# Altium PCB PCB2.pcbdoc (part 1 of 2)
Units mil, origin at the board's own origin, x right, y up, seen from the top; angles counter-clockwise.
Board outline 3540 x 3355 mil, 4 copper layers (Top Layer, GND, PWR, Bottom Layer), stack 62.5 mil thick; 130 components, 101 nets, 421 pads, 287 vias.
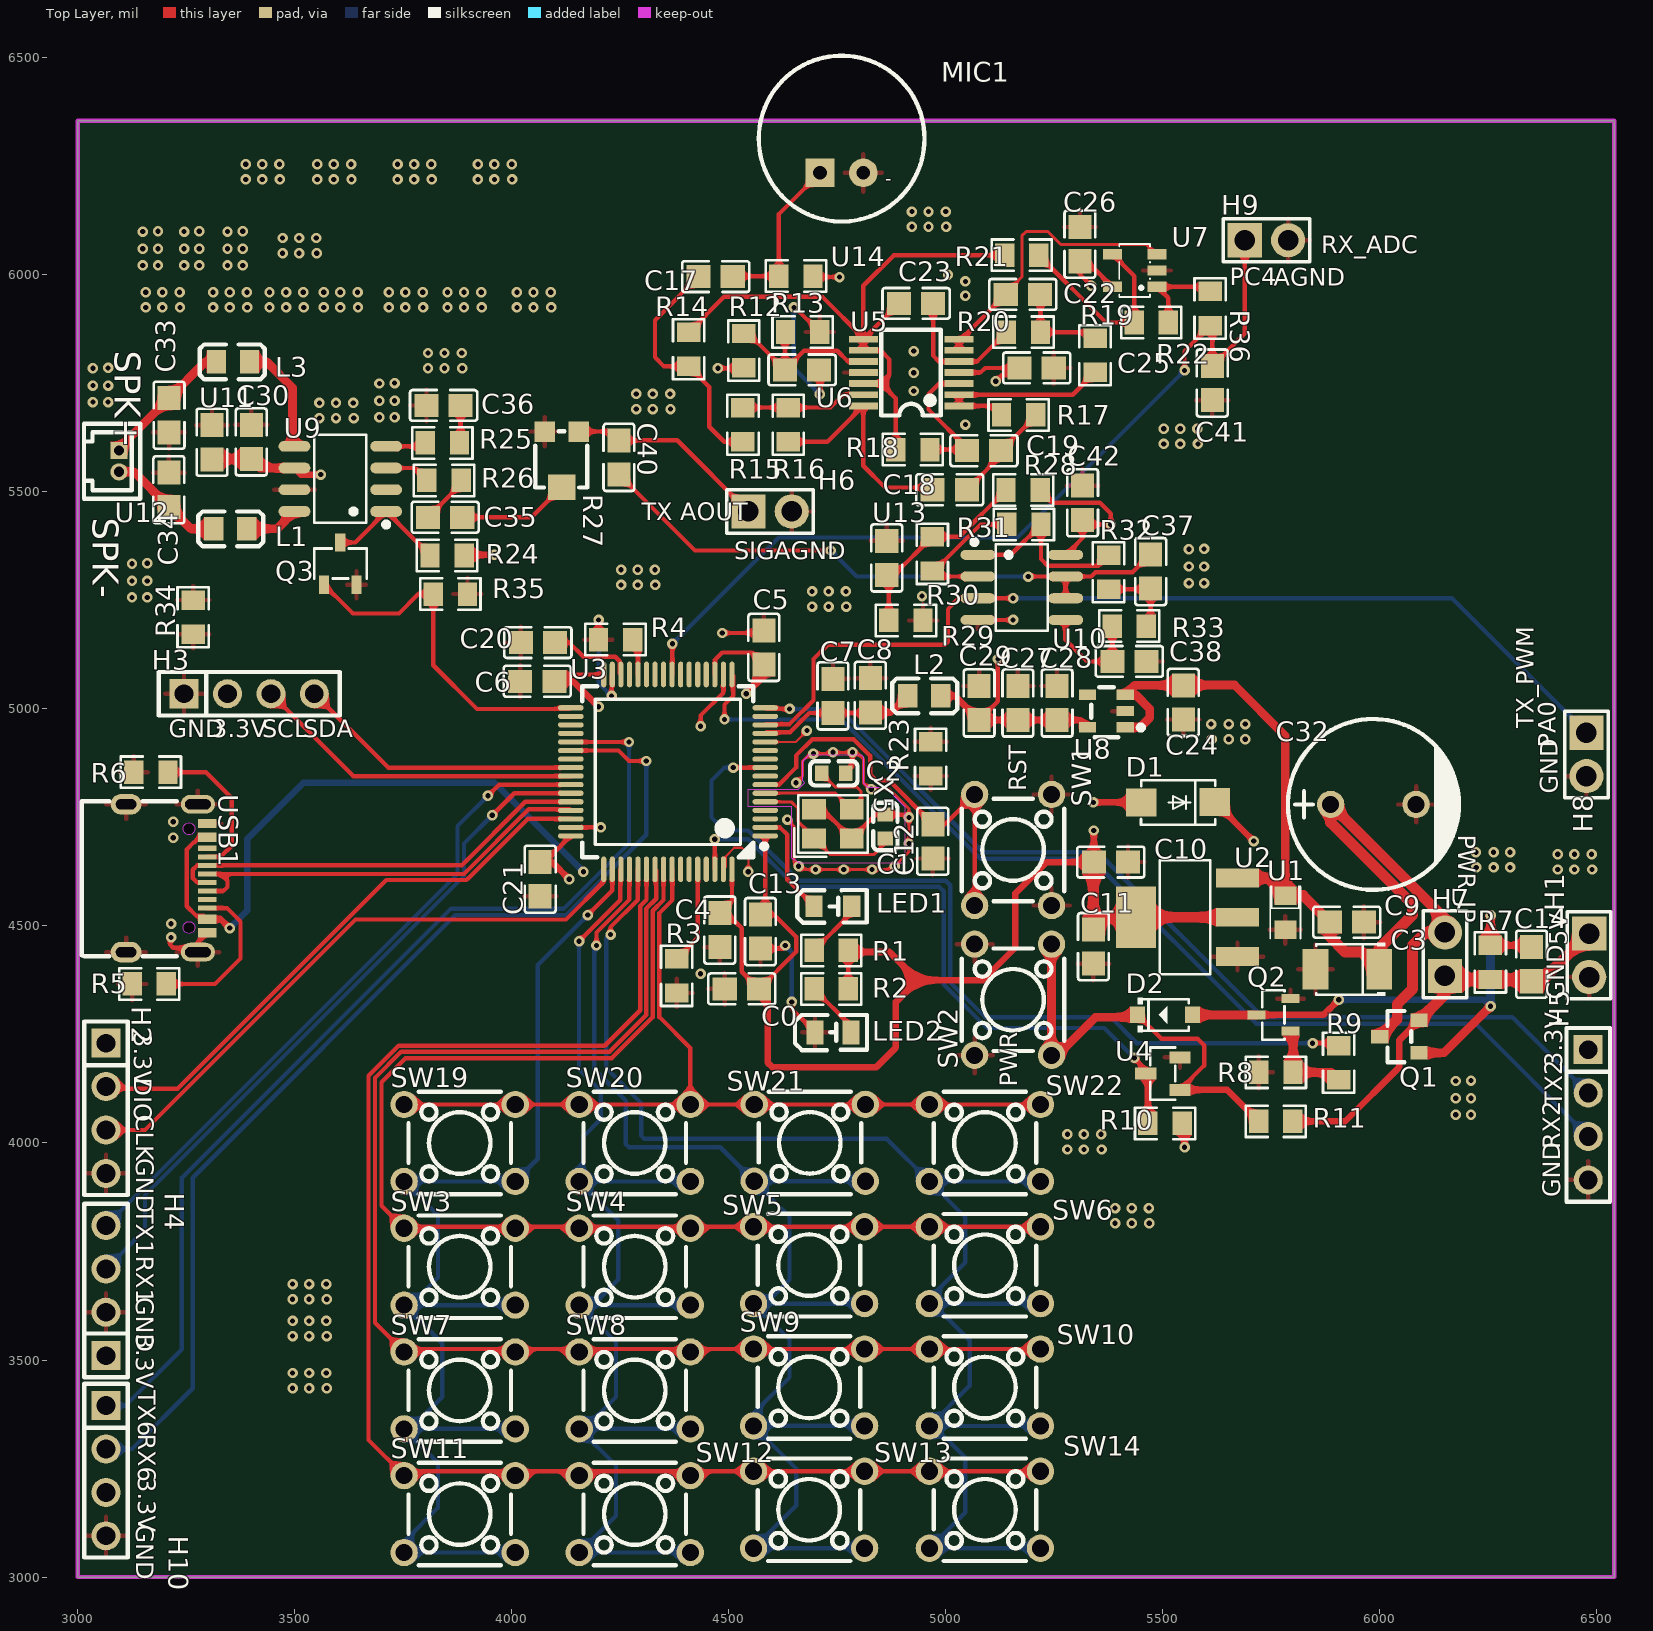
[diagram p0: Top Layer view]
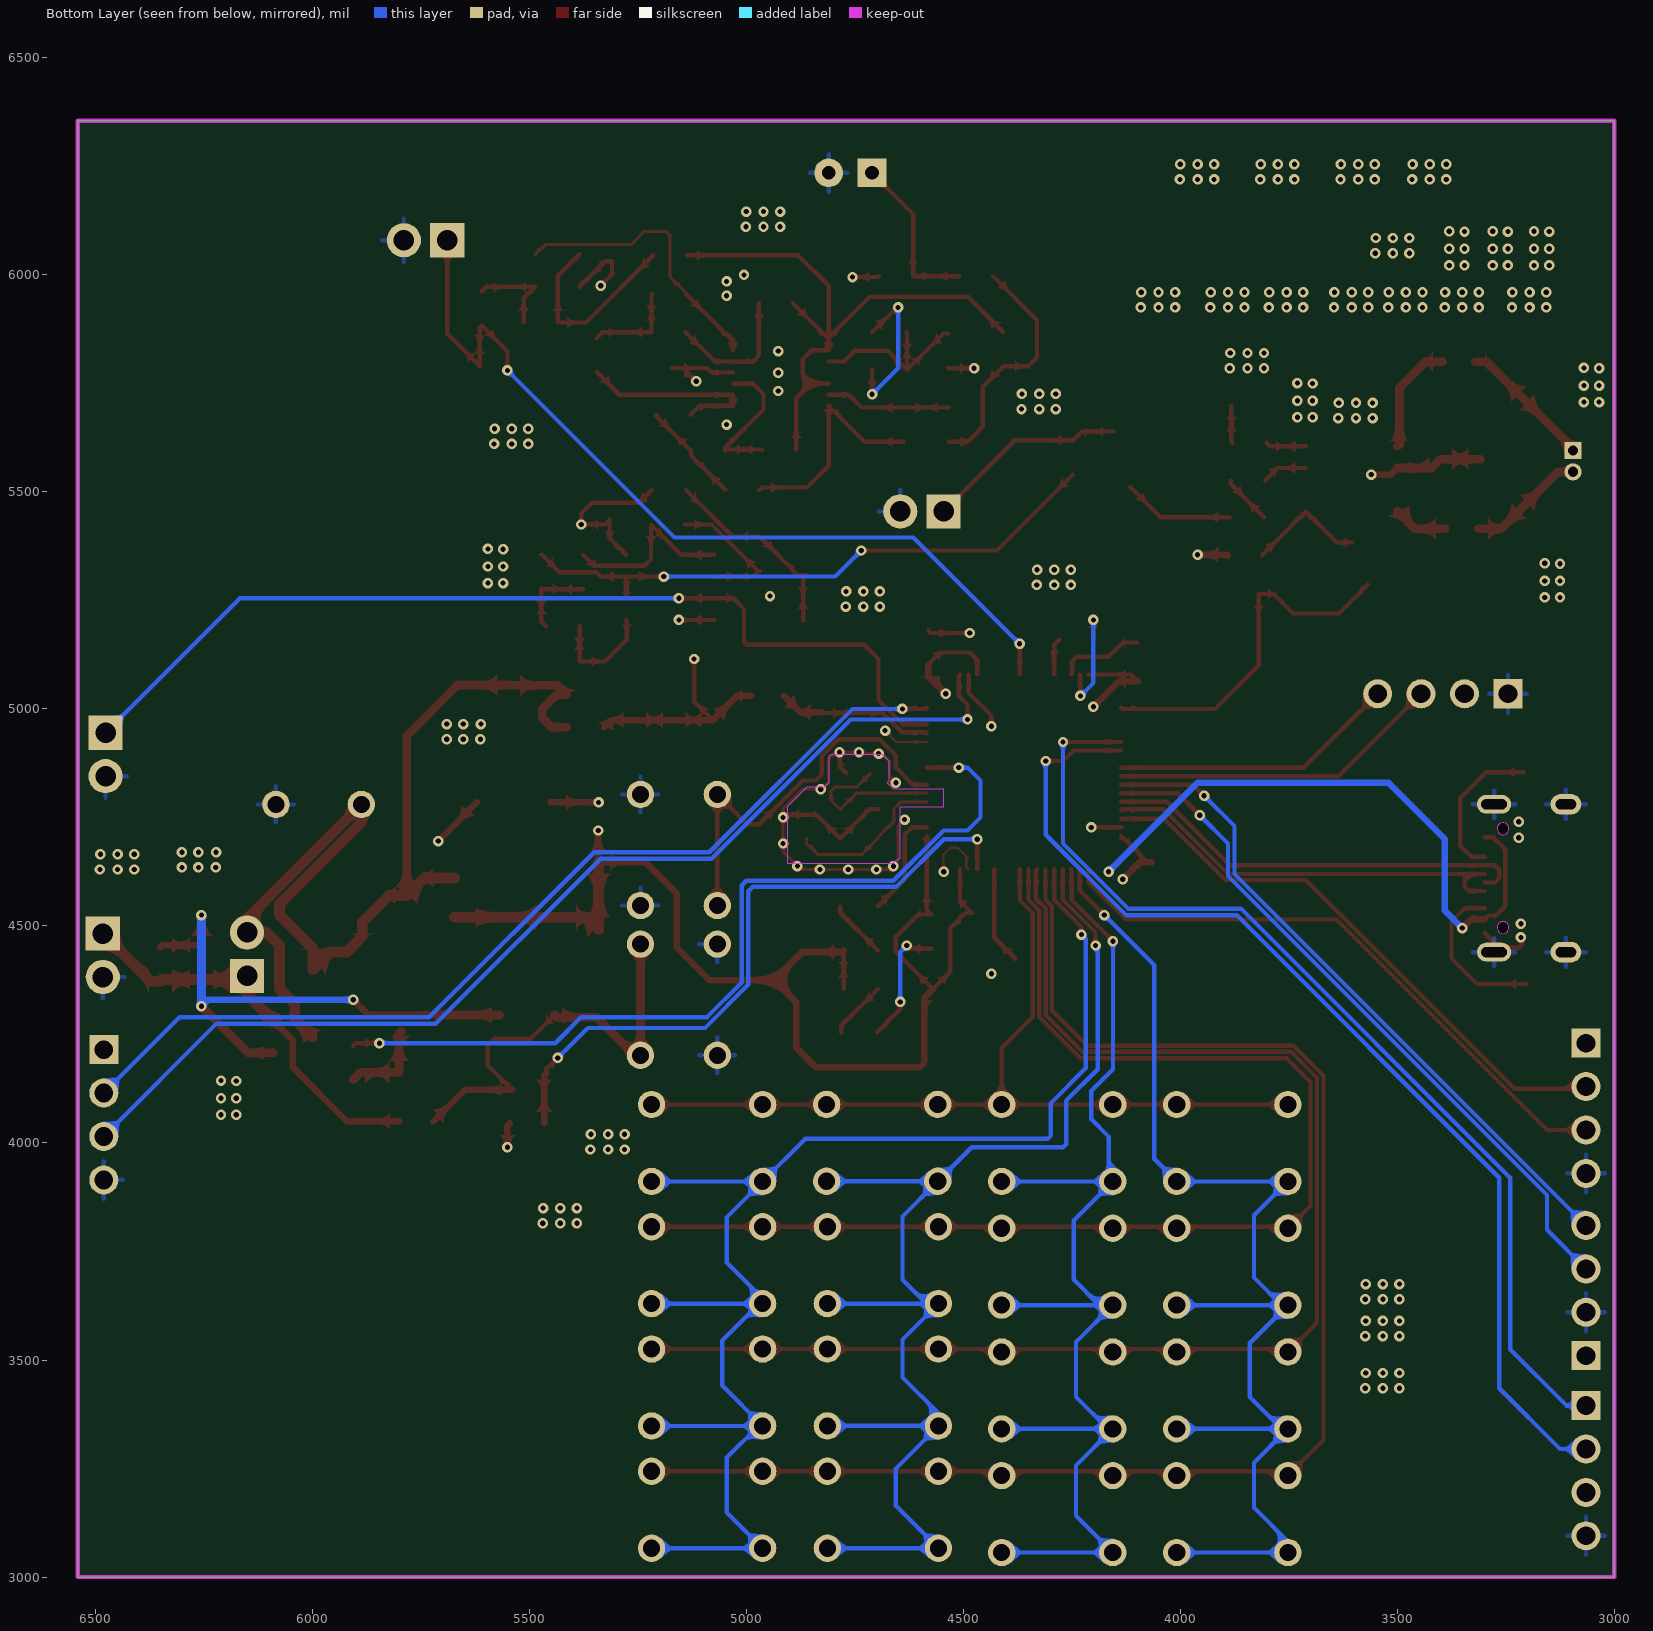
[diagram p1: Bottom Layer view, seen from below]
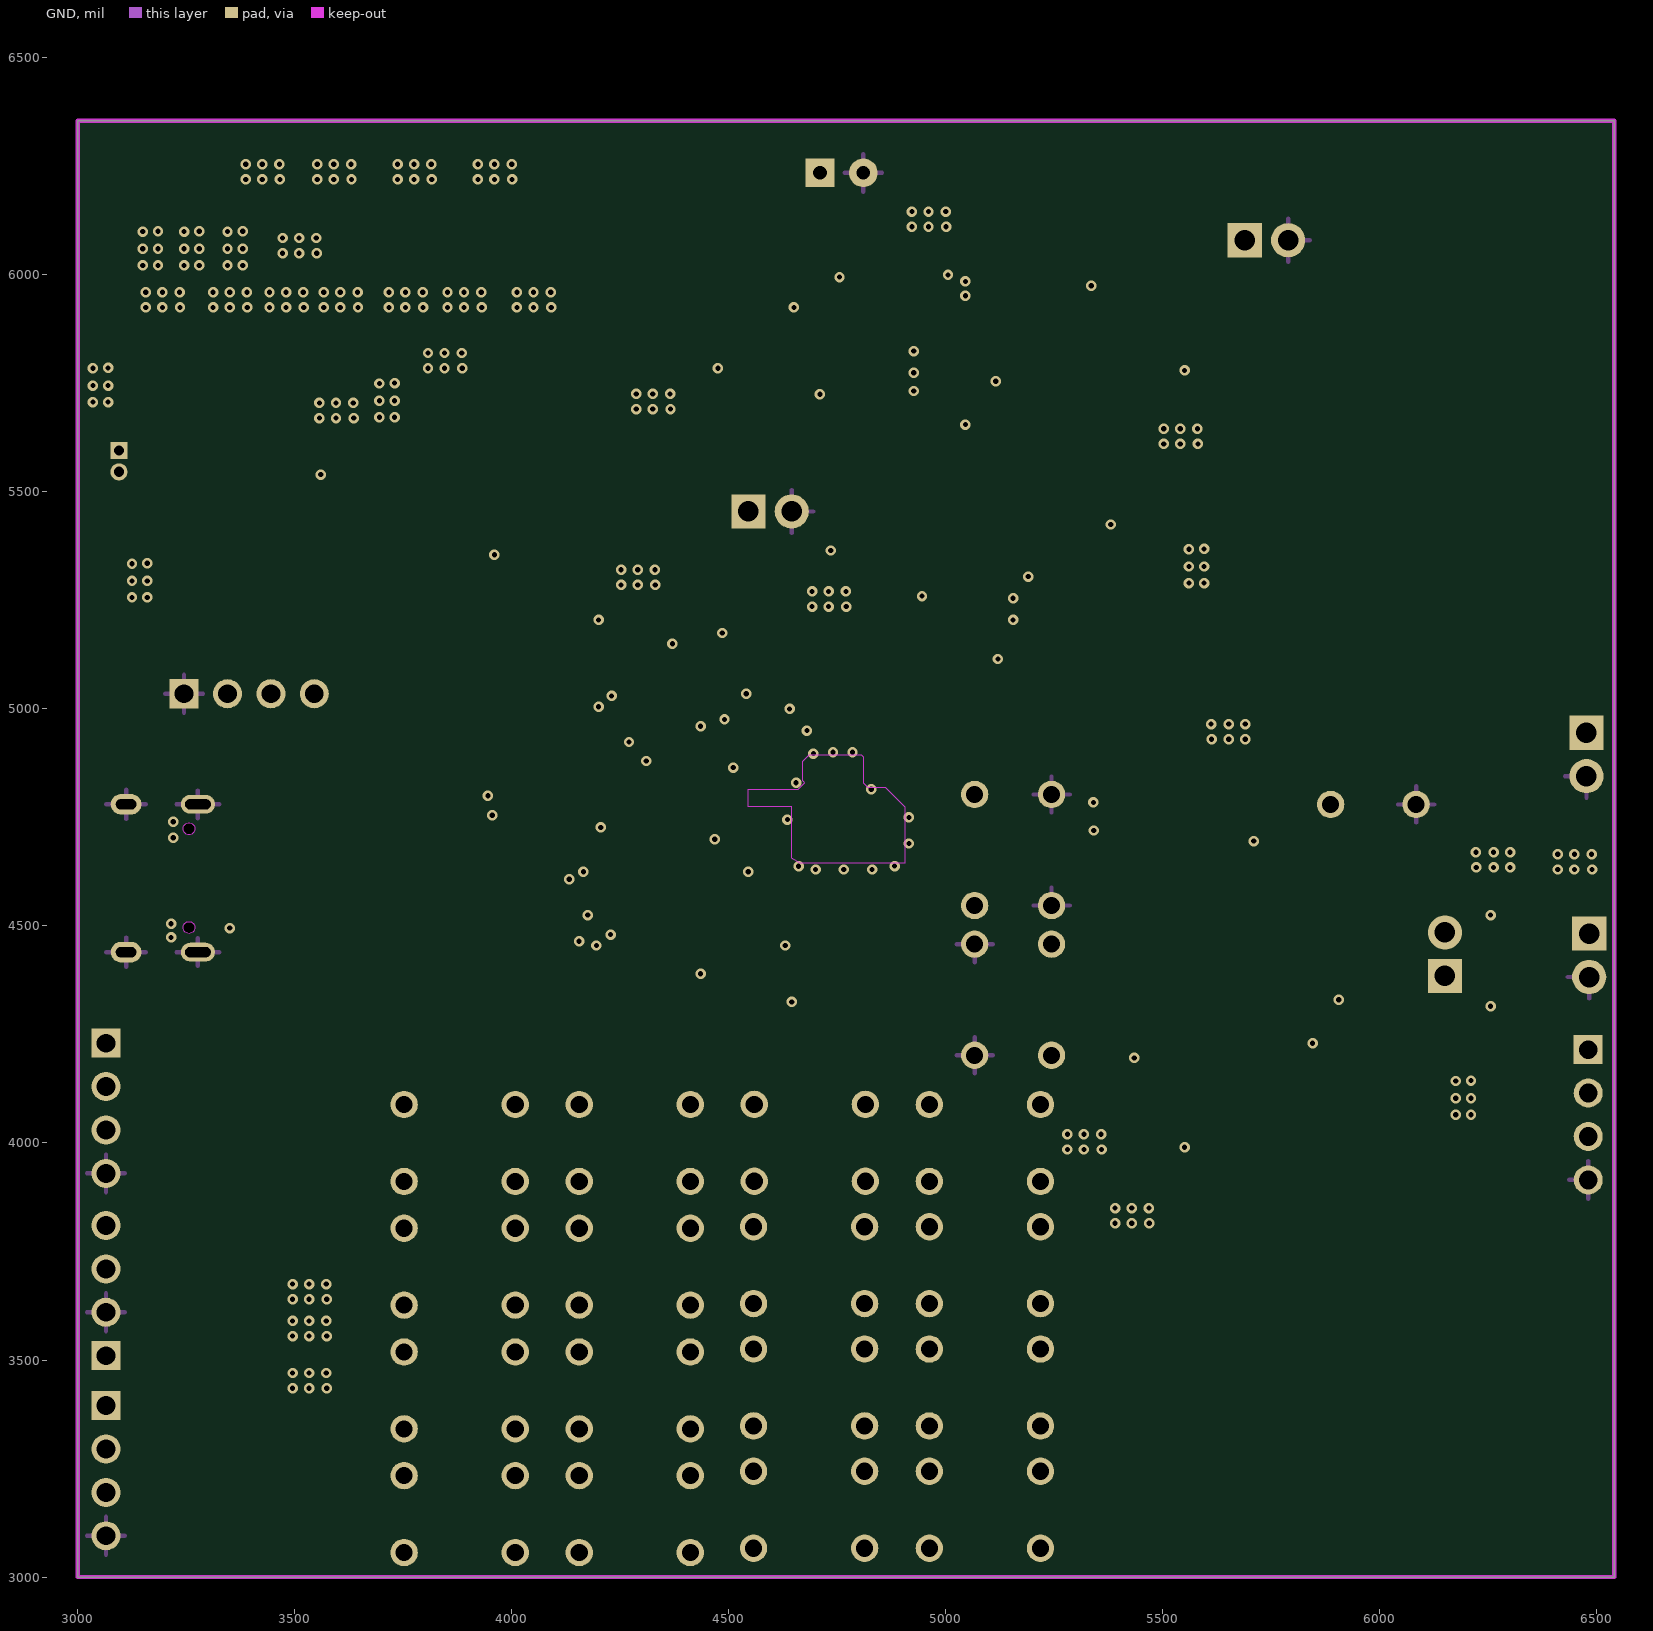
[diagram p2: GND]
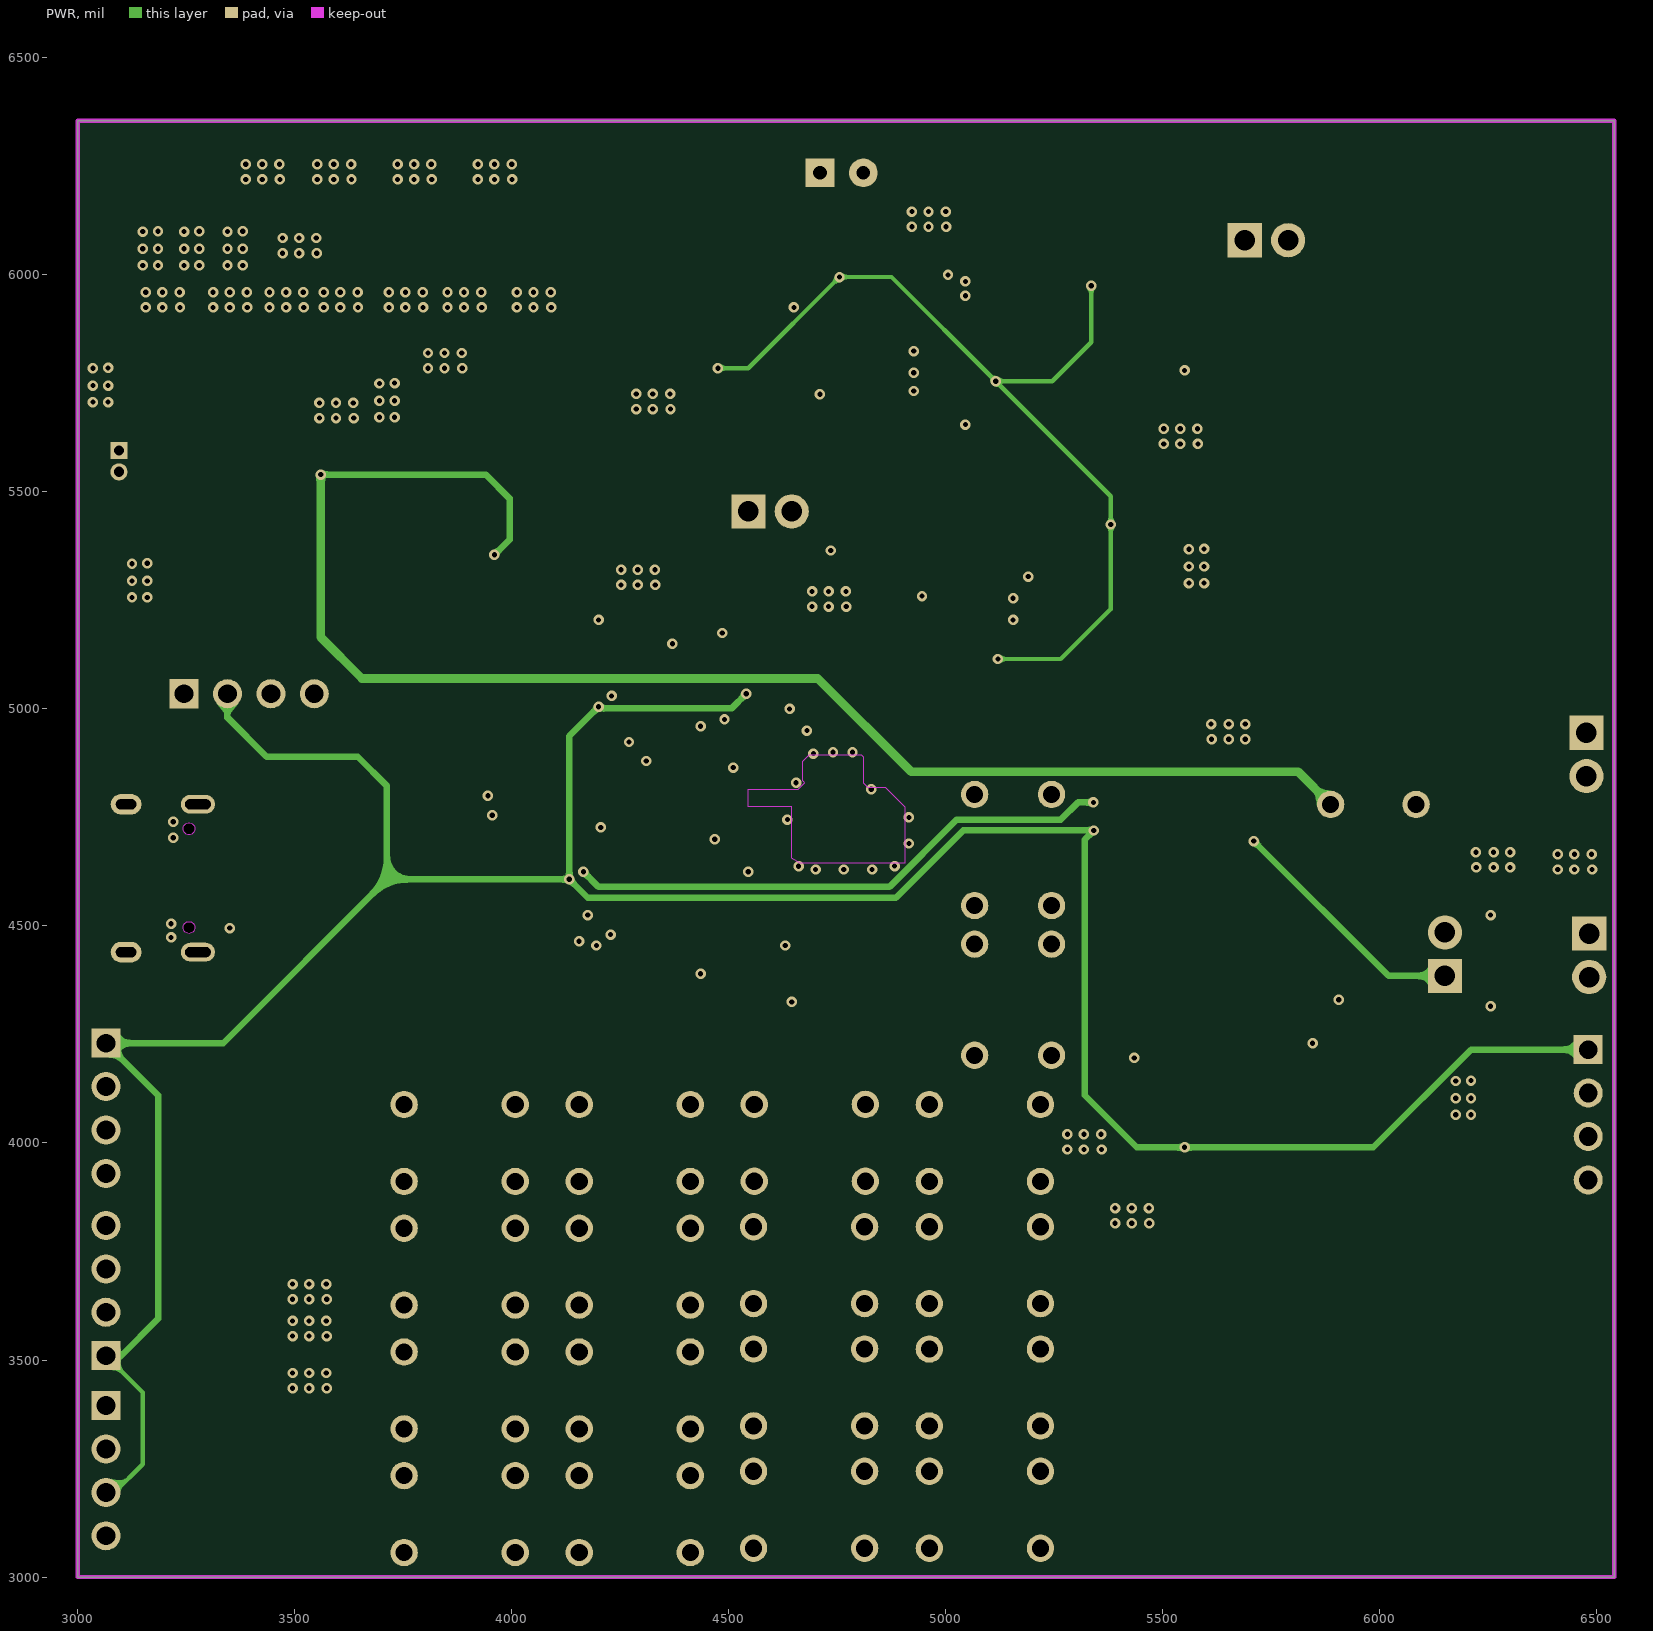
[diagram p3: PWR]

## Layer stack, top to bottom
Top Layer: signal copper 1.4
Dielectric1: surface 8.3, 7628 RC49% 8.6mil, Dk 0
GND: signal copper 0.6
Dielectric2: surface 41.9, 1.1mm H/HOZ Copper, Dk 0
PWR: signal copper 0.6
Dielectric3: surface 8.3, 7628 RC49% 8.6mil, Dk 0
Bottom Layer: signal copper 1.4

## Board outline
3000,6355 3000,3000 6540,3000 6540,6355

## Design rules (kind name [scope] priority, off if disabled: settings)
BoardOutlineClearance copperThickness1oz [All] p0: genericclearance=10 ignorepadtopadclearanceinfootprint=FALSE except(0: Arc-SplitContinuation Track-SplitContinuation SMDPad-SplitContinuation THPad-SplitContinuation Via-SplitContinuation Fill-SplitContinuation Poly-SplitContinuation Region-SplitContinuation Text-SplitContinuation)
BoardOutlineClearance copperThickness2oz [All] p0: genericclearance=10 ignorepadtopadclearanceinfootprint=FALSE except(0: Arc-SplitContinuation Track-SplitContinuation SMDPad-SplitContinuation THPad-SplitContinuation Via-SplitContinuation Fill-SplitContinuation Poly-SplitContinuation Region-SplitContinuation Text-SplitContinuation)
BoardOutlineClearance otherClearance [All] p0: genericclearance=10 ignorepadtopadclearanceinfootprint=FALSE except(0: Arc-SplitContinuation Track-SplitContinuation SMDPad-SplitContinuation THPad-SplitContinuation Via-SplitContinuation Fill-SplitContinuation Poly-SplitContinuation Region-SplitContinuation Text-SplitContinuation)
Clearance copperThickness1oz [All] p1: gap=7 ignorepadtopadclearanceinfootprint=FALSE
Clearance copperThickness2oz [All] p1: gap=7 ignorepadtopadclearanceinfootprint=FALSE
Clearance otherClearance [All] p1: gap=7 ignorepadtopadclearanceinfootprint=FALSE
DiffPairsRouting differentialPair [All] p1: maxuncoupledlength=10 minlimit=6 maxlimit=Infinity mostfreqgap=6 toplayer_minwidth=5 toplayer_prefwidth=10 toplayer_maxwidth=100 bottomlayer_minwidth=5 bottomlayer_prefwidth=10 bottomlayer_maxwidth=100 midlayer1_minwidth=5 midlayer1_prefwidth=10 midlayer1_maxwidth=100 midlayer2_minwidth=5 midlayer2_prefwidth=10 midlayer2_maxwidth=100
PasteMaskExpansion pasteMaskExpansion [All] p1: expansion=0
PlaneConnect innerPlane [All] p1: planeconnectstyle=Relief reliefexpansion=20 reliefentries=4 reliefconductorwidth=10 reliefairgap=10
PolygonConnect copperRegion [All] p1: connectstyle=Relief reliefentries=4 reliefconductorwidth=10 polygonreliefangle="90 Angle" airgapwidth=10
RoutingVias viaSize [All] p1: viastyle="Through Hole" holewidth=12.0078 minholewidth=11.811 maxholewidth=248.0314 width=12.0078 minwidth=11.811 maxwidth=248.0314
SolderMaskExpansion solderMaskExpansion [IsVia] p1: useseparateexpansions=TRUE expansion=-1000 expansionbottom=-1000
SolderMaskExpansion solderMaskExpansion [All] p2: useseparateexpansions=TRUE expansion=2 expansionbottom=2
Width copperThickness1oz [All] p1: maxlimit=100 minlimit=5 preferedwidth=10
Width copperThickness2oz [All] p1: maxlimit=100 minlimit=8 preferedwidth=10

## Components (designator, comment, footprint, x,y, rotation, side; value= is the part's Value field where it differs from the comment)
C0 "4.7uF" C0805#1 4530,4355 r0 top
C1 "8pF" C0603 4860.8,4729 r270 top
C2 "8pF" C0603 4741.9,4851.6 r180 top
C3 "100uF" CASE-B_3528 5925,4400 r180 top
C4 "100nF" C0805#2 4479.4,4490.6 r90 top
C5 "100nF" C0805#2 4580.8,5141.6 r270 top
C6 "100nF" C0805#2 4058.7,5063.7 r0 top
C7 "100nF" C0805#1 4740,5030 r270 top
C8 "1uF" C0805#2 4826.1,5031.6 r270 top
C9 "100nF" C0805#3 5923.7,4508.7 r180 top
C10 "100nF" C0805#3 5380.2,4647.3 r180 top
C11 "10uF" C0805#3 5340,4452.5 r90 top
C12 "100nF" C0805#1 4970,4695 r90 top
C13 "100nF" C0805#3 4572.9,4487.1 r90 top
C14 "1uF" C0805#3 6349.4,4412.1 r90 top
C17 "1uF" C0805#2 4469.8,5996.1 r180 top
C18 "100nF" C0805#1 5009,5505 r0 top
C19 "100nF" C0805#3 5087.7,5595 r180 top
C20 "4.7uF" C0805#2 4060.3,5152.9 r0 top
C21 "100nF" C0805#2 4065.5,4607.8 r90 top
C22 "2.2nF" C0805#2 5177.5,5955 r180 top
C23 "1nF" C0805#3 4931.4,5934.3 r0 top
C24 "1uF" C0805#1 5547.1,5014.9 r90 top
C25 "100nF" C0805#3 5209.4,5785.6 r0 top
C26 "100nF" C0805#1 5309,6070.9 r90 top
C27 "2.2uF" C0805#2 5166,5013.7 r270 top
C28 "10uF" C0805#2 5256.3,5013.7 r270 top
C29 "100nF" C0805#2 5076.6,5013.7 r270 top
C30 "1uF" C0805#1 3400,5615 r270 top
C32 "470uF" CAP-TH_BD10.0-P5.00-D0.6-FD 5985,4780 r0 top
C33 "220pF" C0805#3 3210.5,5676.7 r90 top
C34 "220pF" C0805#1 3210,5505 r90 top
C35 "1uF" C0805#3 3846.5,5441.5 r180 top
C36 "1uF" C0805#1 3842.8,5699.1 r0 top
C37 "1.8nF" C0805#2 5472,5316.5 r270 top
C38 "1.8nF" C0805#2 5422.9,5109.3 r0 top
C40 "1uF" C0805#2 4247,5579.5 r270 top
C41 "2.2nF" C0805#1 5614,5750.9 r90 top
C42 "100nF" C0805#1 5315,5475 r90 top
D1 "SS14" SMA_L4.3-W2.6-LS5.0-FD 5535,4785 r0 top
D2 "B5817W" SOD-123_L2.7-W1.6-LS3.7-FD 5505,4295 r180 top
H1 "PZ254V-11-02P" HDR-TH_2P-P2.54-V-M 6482.2,4432.3 r270 top
H2 "PZ254V-11-04P" HDR-TH_4P-P2.54-V-M 3065,4080 r270 top
H3 "PM254V-11-04-H85" HDR-TH_4P-P2.54-V-F 3395,5035 r0 top
H4 "PZ254V-11-04P" HDR-TH_4P-P2.54-V-M 3065,3660 r90 top
H5 "PZ254V-11-04P" HDR-TH_4P-P2.54-V-M 6480,4065 r270 top
H6 "PZ254V-11-02P" HDR-TH_2P-P2.54-V-M 4595,5455 r0 top
H7 "PZ254V-11-02P" HDR-TH_2P-P2.54-V-M 6150,4435 r90 top
H8 "PZ254V-11-02P" HDR-TH_2P-P2.54-V-M 6475.9,4895.1 r270 top
H9 "PZ254V-11-02P" HDR-TH_2P-P2.54-V-M 5738.6,6079.8 r0 top
H10 "PZ254V-11-04P" HDR-TH_4P-P2.54-V-M 3065,3245 r270 top
L1 "BLM21PG221SN1D" L0805#1 3351.1,5415 r180 top
L2 "CBW201209U102T" L0805#2 4950,5030 r180 top
L3 "BLM21PG221SN1D" L0805#3 3357.7,5799.7 r0 top
LED1 "GL0805UB01" LED0805-RD_BLUE 4740,4545 r0 top
LED2 "GL0805UR01" LED0805-R-RD_RED 4740,4255 r0 top
MIC1 "GMI9745P-56DB" MIC-TH_BD9.7-P2.54-D0.8-L-FD 4760,6235 r0 top
Q1 "AO3401A" SOT-23_L2.9-W1.3-P1.90-LS2.4-BR 6045,4245 r0 top
Q2 "S8050" SOT-23-3_L2.9-W1.3-P1.90-LS2.3-BR 5755,4295 r0 top
Q3 "2N7002K-T1-GE3" SOT-23-3_L2.9-W1.6-P1.90-LS2.8-BR 3605,5335 r270 top
R1 "1.5kΩ" R0805#1 4735.9,4443.5 r180 top
R2 "5.1kΩ" R0805#1 4735.9,4354.8 r180 top
R3 "10kΩ" R0805#1 4380,4385 r270 top
R4 "10kΩ" R0805#2 4239.1,5159.7 r180 top
R5 "5.1kΩ" R0805#3 3164.9,4366.4 r0 top
R6 "5.1kΩ" R0805#1 3168.6,4854.3 r180 top
R7 "100kΩ" R0805#2 6254.4,4416 r270 top
R8 "100kΩ" R0805#3 5760.6,4162.8 r0 top
R9 "10kΩ" R0805#1 5905,4185 r270 top
R10 "10kΩ" R0805#1 5505,4045 r0 top
R11 "100kΩ" R0805#1 5760,4050 r0 top
R12 "10kΩ" R0805#2 4534.4,5825.6 r90 top
R13 "10kΩ" R0805#1 4670,5868.4 r0 top
R14 "100kΩ" R0805#1 4407.6,5828.6 r270 top
R15 "4.7kΩ" R0805#1 4532.6,5654.9 r90 top
R16 "100kΩ" R0805#1 4636.9,5654.9 r90 top
R17 "1.5kΩ" R0805#3 5167.7,5677.4 r180 top
R18 "3.3kΩ" R0805#1 4924,5597.6 r0 top
R19 "15kΩ" R0805#1 5343.9,5814.9 r90 top
R20 "15kΩ" R0805#2 5178.9,5868 r180 top
R21 "47kΩ" R0805#2 5174.7,6045.3 r0 top
R22 "47kΩ" R0805#3 5473.3,5890.3 r180 top
R23 "0Ω" R0805#1 4965,4885 r270 top locked
R24 "10kΩ" R0805#2 3850.9,5353.5 r180 top
R25 "100Ω" R0805#3 3840.1,5612.9 r180 top
R26 "100Ω" R0805#2 3843.9,5526.5 r180 top
R27 "10kΩ" RES-ADJ-SMD_JER33X-1-14 4115,5575 r180 top
R28 "10kΩ" R0805#1 5178.1,5504.4 r180 top
R29 "10kΩ" R0805#3 4908.2,5203.8 r0 top
R30 "47kΩ" R0805#3 4968.9,5357.2 r270 top
R31 "47kΩ" R0805#1 5180,5425 r180 top
R32 "10kΩ" R0805#1 5375,5315 r270 top
R33 "10kΩ" R0805#3 5422.6,5190.9 r180 top
R34 "0Ω" R0805#1 3266.1,5211.4 r90 top
R35 "100kΩ" R0805#2 3858.6,5264.7 r180 top
R36 "1kΩ" R0805#3 5609,5922.5 r270 top
SW1 "SH-6X6X4.3H-CJ" SW-TH_SH-6X6X4.3H-CJ#1 5155,4675 r90 top
SW2 "SH-6X6X4.3H-CJ" SW-TH_SH-6X6X4.3H-CJ#1 5155,4330 r90 top
SW3 "SH-6X6X4.3H-CJ" SW-TH_SH-6X6X4.3H-CJ#1 3880,3715 r0 top
SW4 "SH-6X6X4.3H-CJ" SW-TH_SH-6X6X4.3H-CJ#2 4283.3,3715 r0 top
SW5 "SH-6X6X4.3H-CJ" SW-TH_SH-6X6X4.3H-CJ#3 4685,3718.6 r0 top
SW6 "SH-6X6X4.3H-CJ" SW-TH_SH-6X6X4.3H-CJ#4 5090,3718.3 r0 top
SW7 "SH-6X6X4.3H-CJ" SW-TH_SH-6X6X4.3H-CJ#1 3880,3430 r0 top
SW8 "SH-6X6X4.3H-CJ" SW-TH_SH-6X6X4.3H-CJ#2 4283.3,3430 r0 top
SW9 "SH-6X6X4.3H-CJ" SW-TH_SH-6X6X4.3H-CJ#1 4685,3436.8 r0 top
SW10 "SH-6X6X4.3H-CJ" SW-TH_SH-6X6X4.3H-CJ#3 5090,3436.7 r0 top
SW11 "SH-6X6X4.3H-CJ" SW-TH_SH-6X6X4.3H-CJ#1 3880,3145 r0 top
SW12 "SH-6X6X4.3H-CJ" SW-TH_SH-6X6X4.3H-CJ#2 4283.3,3145 r0 top
SW13 "SH-6X6X4.3H-CJ" SW-TH_SH-6X6X4.3H-CJ#1 4685,3155 r0 top
SW14 "SH-6X6X4.3H-CJ" SW-TH_SH-6X6X4.3H-CJ#1 5090,3155 r0 top
SW19 "SH-6X6X4.3H-CJ" SW-TH_SH-6X6X4.3H-CJ#1 3880,4000 r0 top
SW20 "SH-6X6X4.3H-CJ" SW-TH_SH-6X6X4.3H-CJ#2 4283.3,4000 r0 top
SW21 "SH-6X6X4.3H-CJ" SW-TH_SH-6X6X4.3H-CJ#5 4686.7,4000.3 r0 top
SW22 "SH-6X6X4.3H-CJ" SW-TH_SH-6X6X4.3H-CJ#1 5090,4000 r0 top
U1 "10uF" CAP-SMD_L2.0-W1.3-FD 5782.3,4530.4 r270 top
U2 "AMS1117-3.3" SOT-223-3_L6.5-W3.4-P2.30-LS7.0-BR 5555,4520 r0 top
U3 "STM32F411RET6" LQFP-64_L10.0-W10.0-P0.50-LS12.0-BL 4360,4855 r90 top locked
U4 "2N7002K" SOT-23-3_L2.9-W1.3-P0.95-LS2.4-BR 5500,4160 r0 top
U5 "MCP6004T-I/ST" TSSOP-14_L5.0-W4.4-P0.65-LS6.4-BL 4920,5775 r90 top
U6 "10uF" C0805#3 4668.7,5781.1 r180 top
U7 "MCP6001T-I/OT" SOT-23-5_L3.0-W1.7-P0.95-LS2.8-BR 5435,6010 r0 top
U8 "TPS7A2033PDBVR" SOT-23-5_L2.9-W1.6-P0.95-LS2.8-BR 5370,4995 r0 top
U9 "PAM8302AADCR" SOP-8_L4.9-W3.9-P1.27-LS6.0-BL 3605,5530 r90 top
U10 "MCP6002T-I/SN" SOIC-8_L4.9-W3.9-P1.27-LS6.0-BL 5175,5280 r270 top
U11 "10uF" C0805#2 3309.4,5614.4 r270 top
U12 "ZX-MX1.25-2PZZ" CONN-TH_2P-P1.25_MEGASTAR_ZX-MX1.25-2PZZ 3095,5570.8 r270 top
U13 "10uF" C0805#2 4863.9,5347.9 r270 top
U14 "2.2kΩ" R0805#3 4654.8,5997.2 r0 top
USB1 "TYPE-C 16PIN 2MD(073)" USB-C-SMD_TYPE-C-16PIN-2MD-073 3205,4610 r270 top
X5 "25MHz" CRYSTAL-SMD_4P-L3.2-W2.5-BL 4740,4735 r0 top

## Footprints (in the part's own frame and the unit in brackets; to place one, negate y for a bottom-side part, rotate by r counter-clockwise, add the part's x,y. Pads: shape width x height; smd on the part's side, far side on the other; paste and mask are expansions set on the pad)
C0603 [mil]
  rect 31.5x35.4 smd: 1(-27.6,0) 2(27.6,0)
  silkscreen extent -55,-28 55,28
C0805#1 [mil]
  rect 55.5x53.1 smd paste-3937 mask+2: 1(-39.4,0) 2(39.4,0)
  silkscreen extent -77,-36 77,36
C0805#2 [mil]
  rect 55.5x53.1 smd paste-3937 mask+2: 1(-39.3,0) 2(39.4,0)
  silkscreen extent -77,-36 77,36
C0805#3 [mil]
  rect 55.5x53.1 smd paste-3937 mask+2: 1(-39.4,0) 2(39.3,0)
  silkscreen extent -77,-36 77,36
CAP-SMD_L2.0-W1.3-FD [mil]
  rect 43.3x51.2 smd paste+0 mask+2: 1(-39.4,0) 2(39.3,0)
  silkscreen extent -62,-35 60,35
CAP-TH_BD10.0-P5.00-D0.6-FD [mil]
  round 63 hole 39.4 paste+0 mask+2: 1(-98.4,0) 2(98.4,0)
  silkscreen extent -197,-197 200,197
CASE-B_3528 [mil]
  rect 59.3x93.5 smd: 1(-73.3,0) 2(73.2,0)
  silkscreen extent -87,-61 72,61
CONN-TH_2P-P1.25_MEGASTAR_ZX-MX1.25-2PZZ [mil]
  rect 39.4x39.4 hole 23.6: 1(-24.6,0)
  round 39.4 hole 23.6: 2(24.6,0)
  silkscreen extent -87,-81 87,49
CRYSTAL-SMD_4P-L3.2-W2.5-BL [mil]
  rect 55.1x47.2 smd: 1(-43.3,-33.5) 2(43.3,-33.5) 3(43.3,33.5) 4(-43.3,33.5)
  silkscreen extent -89,-75 80,66
HDR-TH_2P-P2.54-V-M [mil]
  rect 78.7x78.7 hole 47.2: 1(-50,0)
  round 78.7 hole 47.2: 2(50,0)
  silkscreen extent -100,-50 100,50
HDR-TH_4P-P2.54-V-F [mil]
  rect 66.9x66.9 hole 43.3: 1(-150,0)
  round 66.9 hole 43.3: 2(-50,0) 3(50,0) 4(150,0)
  silkscreen extent -208,-50 208,50
HDR-TH_4P-P2.54-V-M [mil]
  rect 66.9x66.9 hole 43.3: 1(-150,0)
  round 66.9 hole 43.3: 2(-50,0) 3(50,0) 4(150,0)
  silkscreen extent -200,-50 200,50
L0805#1 [mil]
  rect 44.6x54.2 smd paste-3937 mask+2: 1(-38,0) 2(38.1,0)
  silkscreen extent -77,-40 73,40
L0805#2 [mil]
  rect 44.6x54.2 smd paste-3937 mask+2: 1(-38,0) 2(38,0)
  silkscreen extent -77,-40 73,40
L0805#3 [mil]
  rect 44.6x54.2 smd paste-3937 mask+2: 1(-38.1,0) 2(38,0)
  silkscreen extent -77,-40 73,40
LED0805-R-RD_RED [mil]
  rect 39.4x55.1 smd: 1(41.3,0) 2(-41.4,0)
  silkscreen extent -88,-41 78,40
LED0805-RD_BLUE [mil]
  rect 39.4x49.2 smd: 1(-43.3,0) 2(43.3,0)
  silkscreen extent -83,-37 78,38
LQFP-64_L10.0-W10.0-P0.50-LS12.0-BL [mil]
  oval 11.8x59.1 smd: 1(-147.6,-223.9) 2(-127.9,-223.9) 3(-108.3,-223.9) 4(-88.6,-223.9) 5(-68.9,-223.9) 6(-49.2,-223.9) 7(-29.5,-223.9) 8(-9.8,-223.9) 9(9.8,-223.9) 10(29.5,-223.9) 11(49.2,-223.9) 12(68.9,-223.9) 13(88.6,-223.9) 14(108.3,-223.9) 15(127.9,-223.9) 16(147.6,-223.9) 33(147.6,223.9) 34(127.9,223.9) 35(108.3,223.9) 36(88.6,223.9) 37(68.9,223.9) 38(49.2,223.9) 39(29.5,223.9) 40(9.8,223.9) 41(-9.8,223.9) 42(-29.5,223.9) 43(-49.2,223.9) 44(-68.9,223.9) 45(-88.6,223.9) 46(-108.3,223.9) 47(-127.9,223.9) 48(-147.6,223.9)
  oval 59.1x11.8 smd: 17(224.4,-147.2) 18(224.4,-127.5) 19(224.4,-107.8) 20(224.4,-88.1) 21(224.4,-68.4) 22(224.4,-48.7) 23(224.4,-29.1) 24(224.4,-9.4) 25(224.4,10.3) 26(224.4,30) 27(224.4,49.7) 28(224.4,69.4) 29(224.4,89) 30(224.4,108.7) 31(224.4,128.4) 32(224.4,148.1) 49(-224.4,148.1) 50(-224.4,128.4) 51(-224.4,108.7) 52(-224.4,89) 53(-224.4,69.4) 54(-224.4,49.7) 55(-224.4,30) 56(-224.4,10.3) 57(-224.4,-9.4) 58(-224.4,-29.1) 59(-224.4,-48.7) 60(-224.4,-68.4) 61(-224.4,-88.1) 62(-224.4,-107.8) 63(-224.4,-127.5) 64(-224.4,-147.2)
  silkscreen extent -197,-228 197,197
MIC-TH_BD9.7-P2.54-D0.8-L-FD [mil]
  rect 66x66 hole 31.5: 1(-50,0)
  round 66 hole 31.5: 2(50,0)
  silkscreen extent -191,-112 191,270
R0805#1 [mil]
  rect 44.6x54.2 smd paste-3937 mask+2: 1(-39.4,0) 2(39.4,0)
  silkscreen extent -69,-36 69,36
R0805#2 [mil]
  rect 44.6x54.2 smd paste-3937 mask+2: 1(-39.3,0) 2(39.4,0)
  silkscreen extent -69,-36 69,36
R0805#3 [mil]
  rect 44.6x54.2 smd paste-3937 mask+2: 1(-39.4,0) 2(39.3,0)
  silkscreen extent -69,-36 69,36
RES-ADJ-SMD_JER33X-1-14 [mil]
  rect 47.2x47.2 smd paste+0 mask+2: 1(39.4,-64) 3(-39.4,-64)
  rect 63x59.1 smd paste+0 mask+2: 2(0,64)
  silkscreen extent -59,-65 61,65
SMA_L4.3-W2.6-LS5.0-FD [mil]
  rect 70.9x63.8 smd: 1(-84.6,-0.4) 2(84.6,0.4)
  silkscreen extent -85,-52 86,51
SOD-123_L2.7-W1.6-LS3.7-FD [mil]
  rect 34.6x37.8 smd: 1(-63.4,0) 2(63.4,0)
  silkscreen extent -54,-39 63,40
SOIC-8_L4.9-W3.9-P1.27-LS6.0-BL [mil]
  oval 23.1x80.5 smd: 1(-75,-101.2) 2(-25,-101.2) 3(25,-101.2) 4(75,-101.2) 5(75,101.2) 6(25,101.2) 7(-25,101.2) 8(-75,101.2)
  silkscreen extent -110,-115 100,60
SOP-8_L4.9-W3.9-P1.27-LS6.0-BL [mil]
  oval 24.8x73.4 smd: 1(-75,-105.6) 2(-25,-105.6) 3(25,-105.6) 4(75,-105.6) 5(75,105.6) 6(25,105.6) 7(-25,105.6) 8(-75,105.6)
  silkscreen extent -111,-111 101,60
SOT-23-3_L2.9-W1.3-P0.95-LS2.4-BR [mil]
  rect 49.2x27.6 smd: 1(39.4,-37.4) 2(39.4,37.4) 3(-39.4,0)
  silkscreen extent -29,-60 29,60
SOT-23-3_L2.9-W1.3-P1.90-LS2.3-BR [mil]
  rect 42.1x20.9 smd: 1(39,-37.4) 2(39,37.4) 3(-39,0)
  silkscreen extent -26,-57 25,57
SOT-23-3_L2.9-W1.6-P1.90-LS2.8-BR [mil]
  rect 42.1x23.6 smd: 1(48.6,-37.4) 2(48.6,37.4) 3(-48.6,0)
  silkscreen extent -35,-61 35,61
SOT-23-5_L2.9-W1.6-P0.95-LS2.8-BR [mil]
  rect 39.4x23.6 smd paste+0 mask+2: 1(43.3,-37.4) 2(43.3,0) 3(43.3,37.4) 4(-43.3,37.4) 5(-43.3,-37.4)
  silkscreen extent -35,-60 85,55
SOT-23-5_L3.0-W1.7-P0.95-LS2.8-BR [mil]
  rect 43.3x23.6 smd: 1(51.2,-37.4) 2(51.2,0) 3(51.2,37.4) 4(-51.2,37.4) 5(-51.2,-37.4)
  silkscreen extent -35,-61 35,61
SOT-23_L2.9-W1.3-P1.90-LS2.4-BR [mil]
  rect 39.4x31.5 smd: 1(45.3,-37.4) 2(45.3,37.4) 3(-45.3,0)
  silkscreen extent -28,-59 28,59
SOT-223-3_L6.5-W3.4-P2.30-LS7.0-BR [mil]
  rect 98.4x43.3 smd: 1(116.9,-90.6) 2(116.9,0) 3(116.9,90.6)
  rect 92.1x141.7 smd: 4(-116.9,0)
  silkscreen extent -62,-131 54,131
SW-TH_SH-6X6X4.3H-CJ#1 [mil]
  round 63 hole 39.4: A(-128,88.6) B(128,88.6) C(-128,-88.6) D(128,-88.6)
  silkscreen extent -118,-118 118,118
SW-TH_SH-6X6X4.3H-CJ#2 [mil]
  round 63 hole 39.4: A(-127.9,88.6) B(128,88.6) C(-127.9,-88.6) D(128,-88.6)
  silkscreen extent -118,-118 118,118
SW-TH_SH-6X6X4.3H-CJ#3 [mil]
  round 63 hole 39.4: A(-128,88.5) B(128,88.5) C(-128,-88.6) D(128,-88.6)
  silkscreen extent -118,-118 118,118
SW-TH_SH-6X6X4.3H-CJ#4 [mil]
  round 63 hole 39.4: A(-128,88.6) B(128,88.6) C(-128,-88.5) D(128,-88.5)
  silkscreen extent -118,-118 118,118
SW-TH_SH-6X6X4.3H-CJ#5 [mil]
  round 63 hole 39.4: A(-128,88.6) B(127.9,88.6) C(-128,-88.5) D(127.9,-88.5)
  silkscreen extent -118,-118 118,118
TSSOP-14_L5.0-W4.4-P0.65-LS6.4-BL [mil]
  rect 15.7x66.9 smd: 1(-76.8,-110.2) 2(-51.2,-110.2) 3(-25.6,-110.2) 4(0,-110.2) 5(25.6,-110.2) 6(51.2,-110.2) 7(76.8,-110.2) 8(76.8,110.2) 9(51.2,110.2) 10(25.6,110.2) 11(0,110.2) 12(-25.6,110.2) 13(-51.2,110.2) 14(-76.8,110.2)
  silkscreen extent -99,-68 98,69
USB-C-SMD_TYPE-C-16PIN-2MD-073 [mil]
  oval 43.3x78.7 hole 23.6 slot 59.1 at 90 deg paste+0 mask+2: 13(-170.3,71.9) 14(170.3,71.9)
  oval 47.2x70.9 hole 23.6 slot 47.2 at 90 deg paste+0 mask+2: 13(-170.3,-93.5) 14(170.3,-93.5)
  rect 21.7x43.3 smd paste-3937 mask+2: A1B12(-126,93.5) A4B9(-94.5,93.5) B1A12(126,93.5) B4A9(94.5,93.5)
  rect 11.8x43.3 smd paste-3937 mask+2: A5(-49.2,93.5) A6(-9.8,93.5) A7(9.8,93.5) A8(49.2,93.5) B5(68.9,93.5) B6(29.5,93.5) B7(-29.5,93.5) B8(-68.9,93.5)
  Board Outline Layer lines w0.1: 113,37.6 116.2,37.8 119.2,38.7 122,40.3 124.3,42.5 126.1,45.2 127.2,48.2 127.6,51.4 127.2,54.6 126.1,57.6 124.3,60.2 122,62.4 119.2,64 116.2,64.9 113,65.1 109.8,64.6 106.9,63.3 104.3,61.4 102.3,58.9 100.8,56.1 100.1,53 100.1,49.8 100.8,46.7 102.3,43.8 104.3,41.4 106.9,39.4 109.8,38.2 113,37.6 ; -114.6,37.6 -111.4,37.8 -108.3,38.7 -105.5,40.3 -103.2,42.5 -101.5,45.2 -100.4,48.2 -100,51.4 -100.4,54.6 -101.5,57.6 -103.2,60.2 -105.5,62.4 -108.3,64 -111.4,64.9 -114.6,65.1 -117.7,64.6 -120.7,63.3 -123.2,61.4 -125.3,58.9 -126.7,56.1 -127.5,53 -127.5,49.8 -126.7,46.7 -125.3,43.8 -123.2,41.4 -120.7,39.4 -117.7,38.2 -114.6,37.6
  Board Outline Layer region: -100,51.4 -100.4,48.2 -101.5,45.2 -103.2,42.5 -105.5,40.3 -108.3,38.7 -111.4,37.8 -114.6,37.6 -117.7,38.2 -120.7,39.4 -123.2,41.4 -125.3,43.8 -126.7,46.7 -127.5,49.8 -127.5,53 -126.7,56.1 -125.3,58.9 -123.2,61.4 -120.7,63.3 -117.7,64.6 -114.6,65.1 -111.4,64.9 -108.3,64 -105.5,62.4 -103.2,60.2 -101.5,57.6 -100.4,54.6
  Board Outline Layer region: -100,51.4 -100.4,48.2 -101.5,45.2 -103.2,42.5 -105.5,40.3 -108.3,38.7 -111.4,37.8 -114.6,37.6 -117.7,38.2 -120.7,39.4 -123.2,41.4 -125.3,43.8 -126.7,46.7 -127.5,49.8 -127.5,53 -126.7,56.1 -125.3,58.9 -123.2,61.4 -120.7,63.3 -117.7,64.6 -114.6,65.1 -111.4,64.9 -108.3,64 -105.5,62.4 -103.2,60.2 -101.5,57.6 -100.4,54.6
  Board Outline Layer region: 127.6,51.4 127.2,48.2 126.1,45.2 124.3,42.5 122,40.3 119.2,38.7 116.2,37.8 113,37.6 109.8,38.2 106.9,39.4 104.3,41.4 102.3,43.8 100.8,46.7 100.1,49.8 100.1,53 100.8,56.1 102.3,58.9 104.3,61.4 106.9,63.3 109.8,64.6 113,65.1 116.2,64.9 119.2,64 122,62.4 124.3,60.2 126.1,57.6 127.2,54.6
  Board Outline Layer region: 127.6,51.4 127.2,48.2 126.1,45.2 124.3,42.5 122,40.3 119.2,38.7 116.2,37.8 113,37.6 109.8,38.2 106.9,39.4 104.3,41.4 102.3,43.8 100.8,46.7 100.1,49.8 100.1,53 100.8,56.1 102.3,58.9 104.3,61.4 106.9,63.3 109.8,64.6 113,65.1 116.2,64.9 119.2,64 122,62.4 124.3,60.2 126.1,57.6 127.2,54.6
  Multi-Layer board cut-out: -100,51.4 -100.4,48.2 -101.5,45.2 -103.2,42.5 -105.5,40.3 -108.3,38.7 -111.4,37.8 -114.6,37.6 -117.7,38.2 -120.7,39.4 -123.2,41.4 -125.3,43.8 -126.7,46.7 -127.5,49.8 -127.5,53 -126.7,56.1 -125.3,58.9 -123.2,61.4 -120.7,63.3 -117.7,64.6 -114.6,65.1 -111.4,64.9 -108.3,64 -105.5,62.4 -103.2,60.2 -101.5,57.6 -100.4,54.6
  Multi-Layer board cut-out: 127.6,51.4 127.2,48.2 126.1,45.2 124.3,42.5 122,40.3 119.2,38.7 116.2,37.8 113,37.6 109.8,38.2 106.9,39.4 104.3,41.4 102.3,43.8 100.8,46.7 100.1,49.8 100.1,53 100.8,56.1 102.3,58.9 104.3,61.4 106.9,63.3 109.8,64.6 113,65.1 116.2,64.9 119.2,64 122,62.4 124.3,60.2 126.1,57.6 127.2,54.6
  silkscreen extent -177,-196 180,24

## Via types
v1: diameter 24, hole 12, Top Layer to Bottom Layer, 287 vias

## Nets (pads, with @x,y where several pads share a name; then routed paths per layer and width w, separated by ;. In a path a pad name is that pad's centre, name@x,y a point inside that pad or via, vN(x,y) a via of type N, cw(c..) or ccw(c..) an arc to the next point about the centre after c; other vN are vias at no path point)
3.3V: C0.2 C4.2 C5.2 C6.2 C10.2 C11.2 C13.2 C21.2 H2.1 H3.2 H4.1 H5.1 H10.3 R1.1 R2.1 R10.2 U2.2 U2.4 U3.1 U3.19 U3.32 U3.48 U3.64 | length 10768.7
  Top Layer w10: C21.2@4075.9,4647.2 U3.48@4136.1,4707.4 ; C6.2@4098.1,5063.7 4113.8,5079.4 U3.32@4211.9,5079.4 ; U3.19@4467.8,5079.4 4467.8,5112.8 4485,5130 4553,5130 C5.2@4580.8,5102.2 ; U3.64@4507.2,4630.6 4507.2,4557.8 C4.2@4479.4,4530 4495,4530 4530,4495 4530,4394.4 C0.2@4569.4,4355 4655,4440.6 4655,4475 4603.6,4526.4 C13.2@4572.9,4526.4 4583.9,4537.5 U3.1@4583.9,4707.4 ; R2.1@4775.3,4354.8 R1.1@4775.3,4443.5
  Top Layer w15: C21.2@4065.5,4647.2 4075.9,4647.2 4092.8,4647.2 v1(4132.5,4607.5) ; C6.2@4098.1,5063.7 4141.3,5063.7 v1(4200,5005) ; v1(4540,5035) 4580.8,5075.8 C5.2@4580.8,5102.2 ; C0.2@4569.4,4355 4589.4,4335 4589.4,4185.6 4600,4175 4840,4175 4885,4220 4885,4325 4935,4375 ; R1.1@4775.3,4443.5 4778.8,4440 4870,4440 4935,4375 ; v1(5340.9,4720) C10.2@5340.9,4647.3 5232.3,4647.3 5160,4575 5160,4450 5085,4375 4935,4375 ; R10.2@5544.4,4045 5550,4039.4 v1(5550,3990)
  Top Layer w25: C10.2@5340.9,4647.3 5340,4646.5 5340,4491.9 5368.1,4520 U2.4@5438.1,4520 U2.2@5671.9,4520
  PWR w10: H10.3@3065,3195 3085,3195 3150,3260 3150,3425 H4.1@3065,3510
  PWR w15: H4.1@3065,3510 3100,3510 3185,3595 3185,4110 H2.1@3065,4230 3335,4230 3712.5,4607.5 ; H3.2@3345,5035 3345,4980 3435,4890 3645,4890 3712.5,4822.5 3712.5,4607.5 ; v1(4540,5035) 4506.2,5001.2 4203.8,5001.2 v1(4200,5005) 4132.5,4937.5 v1(4132.5,4607.5) ; H5.1@6480,4215 6210,4215 5985,3990 v1(5550,3990) 5440,3990 5320,4110 5320,4699.1 v1(5340.9,4720) 5040,4720 4885,4565 4175,4565 v1(4132.5,4607.5) ; 3712.5,4607.5 v1(4132.5,4607.5)
5V_IN: C14.1 D1.2 H1.1 H7.1 Q1.2 R7.2 R11.2 | length 1629.8
  Top Layer w15: D1.2@5619.6,4785.4 v1(5709.6,4695.4) ; R11.2@5799.4,4050 5920,4050 6045,4175 6045,4237.1 Q1.2@6090.3,4282.4
  Top Layer w25: Q1.2@6090.3,4282.4 6150,4342.1 H7.1@6150,4385 6158.4,4376.6 R7.2@6254.4,4376.6 6345.5,4376.6 C14.1@6349.4,4372.7 6372.6,4372.7 H1.1@6482.2,4482.3
  PWR w15: v1(5709.6,4695.4) 6020,4385 H7.1@6150,4385
5V_SYS: C3.1 C9.2 C24.2 C30.2 C32.1 H7.2 Q1.3 R24.1 U1.1 U2.3 U8.1 U8.3 U9.6 U11.2 | length 6405.9
  Top Layer w15: U9.6@3499.4,5555 3514.4,5540 v1(3560,5540) ; R24.1@3890.2,5353.5 3891.7,5355 v1(3960,5355)
  Top Layer w20: U11.2@3309.4,5575 3310,5575.6 C30.2@3400,5575.6 3420.6,5555 U9.6@3499.4,5555 ; U8.1@5413.3,4957.6 5447.6,4957.6 5470,4980 5470,5000 5437.6,5032.4 U8.3@5413.3,5032.4 5435.2,5054.3 C24.2@5547.1,5054.3 5547.8,5055 5665,5055 5782.3,4937.7 U1.1@5782.3,4569.8
  Top Layer w25: U2.3@5671.9,4610.6 5741.6,4610.6 U1.1@5782.3,4569.8 5823.3,4569.8 C9.2@5884.4,4508.7 5884.4,4475.6 5920,4440 5958.3,4440 C3.1@5998.3,4400 5998.3,4448.3 6075,4525 6075,4550 5886.6,4738.4 C32.1@5886.6,4780 6150,4516.6 H7.2@6150,4485 6105,4485 6075,4455 6075,4355 6040,4320 6040,4285.3 Q1.3@5999.7,4245
  PWR w15: v1(3560,5540) 3940,5540 3995,5485 3995,5390 v1(3960,5355)
  PWR w20: v1(3560,5540) 3560,5165 3655,5070 4705,5070 4920,4855 5811.6,4855 C32.1@5886.6,4780
$1N58: LED1.2 R1.2 | length 137.5
  Top Layer w10: R1.2@4696.5,4443.5 4783.3,4530.3 LED1.2@4783.3,4545
$1N62: LED2.1 R2.2 | length 134.9
  Top Layer w10: R2.2@4696.5,4354.8 4781.3,4269.9 LED2.1@4781.3,4255
$1N82: R5.2 USB1.B5 | length 369.5
  Top Layer w10: R5.2@3204.2,4366.4 3316.4,4366.4 3375,4425 3375,4510 3343.9,4541.1 USB1.B5@3298.5,4541.1
$1N83: R6.1 USB1.A5 | length 348.7
  Top Layer w10: R6.1@3208,4854.3 3295.7,4854.3 3355,4795 3355,4685 3329.2,4659.2 USB1.A5@3298.5,4659.2
$1N139: C20.2 U3.30 | length 198.3
  Top Layer w10: C20.2@4099.7,5152.9 4132.1,5152.9 4165,5120 4238.5,5120 4248.5,5110 4248.5,5082.2 U3.30@4251.3,5079.4
$1N222: Q2.1 R8.2 R9.2 | length 209.5
  Top Layer w20: Q2.1@5794,4257.6 5799.9,4251.7 R8.2@5799.9,4162.8 5887.8,4162.8 R9.2@5905,4145.6
$1N236: D2.2 R11.1 SW2.C SW2.D U4.1 | length 1011.4
  Top Layer w10: D2.2@5441.6,4295 5496.6,4240 5580,4240 5595,4225 5595,4178.2 U4.1@5539.4,4122.6
  Top Layer w15: U4.1@5539.4,4122.6 5648,4122.6 R11.1@5720.6,4050
  Top Layer w20: SW2.D@5243.6,4457.9 5243.6,4202.1 5257.1,4202.1 5345,4290 5436.6,4290 D2.2@5441.6,4295
$1N237: C14.2 D2.1 Q1.1 Q2.3 R7.1 | length 1293
  Top Layer w15: Q2.3@5716,4295 5870,4295 v1(5905,4330) ; R7.1@6254.4,4455.3 6345.5,4455.3 C14.2@6349.4,4451.4
  Top Layer w20: D2.1@5568.4,4295 Q2.3@5716,4295 ; Q1.1@6090.3,4207.6 6147.6,4207.6 v1(6255,4315) ; R7.1@6254.4,4455.3 6255,4456 v1(6255,4525)
  Bottom Layer w15: v1(5905,4330) 6240,4330 v1(6255,4315)
  Bottom Layer w20: v1(6255,4315) v1(6255,4525)
$1N249: R12.2 R13.1 U5.10 U6.2 | length 426.2
  Top Layer w10: R12.2@4534.4,5865 4545.4,5865 U6.2@4629.4,5781.1 ; R13.1@4630.6,5868.4 4629.4,5867.2 U6.2@4629.4,5781.1 ; U5.10@4809.8,5800.6 4774.4,5800.6 4750,5825 4673.3,5825 U6.2@4629.4,5781.1
$1N252: C23.1 R14.1 R18.1 R21.1 U5.8 U5.9 U5.12 | length 1434.6
  Top Layer w10: R14.1@4407.6,5868 4489.6,5950 4715,5950 U5.8@4809.8,5855.2 ; U5.12@4809.8,5749.4 4849.4,5749.4 4850,5750 ; R18.1@4884.6,5597.6 4884.6,5715.4 4850,5750 ; C23.1@4892,5934.3 U5.8@4809.8,5852 ; R21.1@5135.4,6045.3 4880.3,6045.3 4809.8,5974.8 U5.8@4809.8,5855.2 ; U5.8@4809.8,5852 U5.8@4809.8,5851.8 U5.9@4809.8,5826.2 4848.8,5826.2 4870,5805 4870,5770 4850,5750 ; U5.8@4809.8,5852 U5.8@4809.8,5855.2
$1N253: R15.2 R16.2 U5.13 | length 289.4
  Top Layer w10: R15.2@4532.6,5694.3 R16.2@4636.9,5694.3 4734.3,5694.3 4763.8,5723.8 U5.13@4809.8,5723.8
$1N254: C18.1 R16.1 U5.14 | length 527.8
  Top Layer w10: R16.1@4636.9,5615.5 4727.1,5615.5 U5.14@4809.8,5698.2 4809.8,5560.2 4860,5510 4964.6,5510 C18.1@4969.6,5505
$1N255: C17.2 R14.2 R15.1 | length 564.6
  Top Layer w10: C17.2@4430.4,5996.1 4330,5895.7 4330,5810 4350.8,5789.2 R14.2@4407.6,5789.2 4455,5741.8 4455,5650 4489.5,5615.5 R15.1@4532.6,5615.5
$1N257: C17.1 MIC1.1 U14.1 | length 383.7
  Top Layer w10: C17.1@4509.1,5996.1 4510.2,5997.2 U14.1@4615.4,5997.2 4615.4,6140.4 MIC1.1@4710,6235
$1N258: C18.2 C19.1 R17.1 | length 238.1
  Top Layer w10: C18.2@5048.4,5505 5127.1,5583.7 C19.1@5127.1,5595 5207.1,5675 R17.1@5207.1,5677.4
$1N259: C19.2 R18.2 U5.3 | length 333
  Top Layer w10: R18.2@4963.4,5597.6 5045.7,5597.6 C19.2@5048.4,5595 5048.4,5601.6 4960,5690 4960,5725 4984.4,5749.4 U5.3@5030.2,5749.4
$1N260: R17.2 R19.1 U5.1 U5.2 | length 467.5
  Top Layer w10: R17.2@5128.4,5677.4 5107.5,5698.2 U5.1@5030.2,5698.2 U5.2@5030.2,5723.8 5292.2,5723.8 R19.1@5343.9,5775.5
$1N261: C22.1 R19.2 R20.1 | length 218.9
  Top Layer w10: C22.1@5216.9,5955 5218.2,5953.6 R20.1@5218.2,5868 5330.2,5868 R19.2@5343.9,5854.3
$1N262: C22.2 U5.6 U5.7 U7.3 | length 663.7
  Top Layer w7: C22.2@5138.1,5955 5138.1,5958.1 5175,5995 5175,6090 5185,6100 5235,6100 5265,6070 5463.6,6070 U7.3@5486.2,6047.4
  Top Layer w10: U5.6@5030.2,5826.2 U5.7@5030.2,5851.8 5034.9,5851.8 C22.2@5138.1,5955
$1N263: C23.2 R20.2 U5.5 | length 322.9
  Top Layer w10: C23.2@4970.7,5934.3 4970.7,5814.3 4985,5800 5029.6,5800 U5.5@5030.2,5800.6 5072.1,5800.6 R20.2@5139.5,5868
$1N266: R21.2 R22.2 U7.4 | length 462
  Top Layer w10: R21.2@5214.1,6045.3 5369.1,5890.3 R22.2@5434,5890.3 5434,5997.2 U7.4@5383.8,6047.4
$1N267: R22.1 R36.1 U7.1 | length 220.5
  Top Layer w10: R22.1@5512.7,5890.3 5512.7,5946.1 U7.1@5486.2,5972.6 5598.3,5972.6 R36.1@5609,5961.9
$1N283: Q3.3 R24.2 U9.1 | length 278.5
  Top Layer w10: Q3.3@3605,5383.6 3639.2,5383.6 U9.1@3710.6,5455 3811.5,5354.1 R24.2@3811.5,5353.5
$1N285: L1.1 U9.8 | length 126.9
  Top Layer w20: L1.1@3389.1,5415 3459.4,5415 U9.8@3499.4,5455
$1N286: L3.2 U9.5 | length 260.9
  Top Layer w20: L3.2@3395.7,5799.7 3435.3,5799.7 3495,5740 3495,5609.4 U9.5@3499.4,5605
$1N293: R26.2 U9.3 | length 105.7
  Top Layer w10: U9.3@3710.6,5555 3776,5555 R26.2@3804.5,5526.5
$1N294: C35.2 R26.1 | length 116.5
  Top Layer w10: C35.2@3807.2,5441.5 3883.2,5517.5 R26.1@3883.2,5526.5
$1N295: C36.2 R25.1 | length 87.3
  Top Layer w10: R25.1@3879.5,5612.9 3882.2,5615.5 C36.2@3882.2,5699.1
$1N296: R25.2 U9.4 | length 93.5
  Top Layer w10: U9.4@3710.6,5605 3792.9,5605 R25.2@3800.8,5612.9
$1N297: C33.2 L3.1 U12.1 | length 312.3
  Top Layer w20: U12.1@3095,5595.4 3095,5600.6 C33.2@3210.5,5716 3294.1,5799.7 L3.1@3319.6,5799.7
$1N298: C34.1 L1.2 U12.2 | length 272.3
  Top Layer w20: U12.2@3095,5546.2 3129.4,5546.2 C34.1@3210,5465.6 3260.6,5415 L1.2@3313,5415
$1N299: C35.1 R27.2 | length 257.9
  Top Layer w10: C35.1@3885.9,5441.5 4045.5,5441.5 R27.2@4115,5511
$1N302: R28.2 R29.1 R30.1 U13.2 | length 462.7
  Top Layer w10: R29.1@4868.8,5203.8 4868.8,5303.6 U13.2@4863.9,5308.5 4880.8,5308.5 R30.1@4968.9,5396.6 5031,5396.6 R28.2@5138.7,5504.4
$1N304: R30.2 R31.2 U10.2 | length 322.3
  Top Layer w10: R30.2@4968.9,5317.9 R30.2@4972.9,5317.9 ; U10.2@5073.8,5305 4985.7,5305 R30.2@4972.9,5317.9 ; R31.2@5140.6,5425 5080,5425 R30.2@4972.9,5317.9
$1N309: R31.1 R32.1 U10.1 | length 426.2
  Top Layer w10: U10.1@5073.8,5355 5149.4,5355 R31.1@5219.4,5425 5219.4,5345.6 5235,5330 5350.6,5330 R32.1@5375,5354.4
$1N310: C37.2 R32.2 R33.1 | length 188
  Top Layer w10: R32.2@5375,5275.6 5470.5,5275.6 C37.2@5472,5277.1 5472,5200.9 R33.1@5462,5190.9
$1N311: C38.1 R33.2 U10.5 | length 256.8
  Top Layer w10: U10.5@5276.2,5205 5275,5203.8 5275,5160 5325.7,5109.3 C38.1@5383.6,5109.3 5383.6,5190.6 R33.2@5383.3,5190.9
$1N313: C37.1 C40.2 U10.6 U10.7 | length 1393.4
  Top Layer w10: C40.2@4247,5540.1 4422.1,5365 v1(4735,5365) ; v1(5190,5305) U10.7@5276.2,5305 ; U10.6@5276.2,5255 U10.7@5276.2,5305 ; C37.1@5472,5355.8 5470.8,5355.8 5430,5315 5345,5315 5335,5305 U10.7@5276.2,5305
  Bottom Layer w10: v1(4735,5365) 4795,5305 v1(5190,5305)
AGND: C7.1 C8.1 C24.1 C25.2 C26.2 C27.1 C28.1 C29.1 C38.2 C41.1 C42.2 H6.2 H9.2 MIC1.2 R13.2 R23.1 R29.2 U3.12 U5.11 U6.1 U7.2 U8.2 U10.4 U13.1 | length 552.7
  Top Layer w5: U3.12@4583.9,4923.9 4653.9,4923.9 v1(4680,4950)
  Top Layer w10: v1(4650,5925) 4652.8,5925 R13.2@4709.4,5868.4 ; U6.1@4708.1,5781.1 4710,5779.2 v1(4710,5725) ; U10.4@5073.8,5205 v1(5155,5205)
  Bottom Layer w10: v1(4650,5925) 4650,5785 v1(4710,5725)
  other v1: 5612.2,4930 5651.9,4930 5690,4930 5611.2,4965 5651.9,4965 5690,4965 4691.9,5235.7 4730,5235.7 4770.7,5235.7 4945,5260 4691.9,5270.7 4730,5270.7 4769.7,5270.7 4251.9,5285.7 4290,5285.7 4330.7,5285.7 5560,5290 5595,5290 4251.9,5320.7 4290,5320.7 4329.7,5320.7 5560,5328.1 5595,5328.1 5560,5367.8 5595,5368.8 5501.9,5610.7 5540,5610.7 5580.7,5610.7 5501.9,5645.7 5540,5645.7 5579.7,5645.7 5045,5655 4286.9,5690.7 4325,5690.7 4365.7,5690.7 4286.9,5725.7 4325,5725.7 4364.7,5725.7 4926.1,5732.5 4926.1,5774.7 4926.1,5824.3 5045,5951.8 5045,5985 5005,6000 4921.9,6110.7 4960,6110.7 5000.7,6110.7 4921.9,6145.7 4960,6145.7 4999.7,6145.7
agnd: 
AMP_MUTE: Q3.1 R35.2 U3.33 | length 821.2
  Top Layer w10: Q3.1@3567.6,5286.4 3634,5220 3740,5220 3784.7,5264.7 R35.2@3819.2,5264.7 3819.2,5100.8 3920,5000 4133.4,5000 U3.33@4136.1,5002.6
AVCC: C25.1 C26.1 C27.2 C28.2 C29.2 C42.1 L2.1 R12.1 R28.1 U5.4 U7.5 U8.5 U10.8 U14.2 | length 3535.2
  Top Layer w10: v1(4475,5785) 4533.1,5785 R12.1@4534.4,5786.3 ; U14.2@4694.1,5997.2 4696.3,5995 v1(4755,5995) ; U5.4@5030.2,5775 5080,5775 5090.6,5785.6 C25.1@5145.6,5785.6 ; C29.2@5076.6,4974.3 5120,5017.7 v1(5120,5115) ; v1(5115,5755) C25.1@5145.6,5785.6 ; C25.1@5170,5785.6 C25.1@5145.6,5785.6 ; R28.1@5217.5,5504.4 5246.9,5475 5355,5475 5380,5450 v1(5380,5425) 5325.6,5425 C42.1@5315,5435.6 5315,5393.8 U10.8@5276.2,5355 ; v1(5335,5975) 5309,6001 C26.1@5309,6031.5 5324.9,6031.5 U7.5@5383.8,5972.6
  Top Layer w15: L2.1@4988,5030 5020.9,5030 C29.2@5076.6,4974.3 C27.2@5166,4974.3 C28.2@5256.3,4974.3 5310,4974.3 U8.5@5326.7,4957.6
  PWR w10: v1(4475,5785) 4545,5785 v1(4755,5995) 4875,5995 v1(5115,5755) ; v1(5120,5115) 5265,5115 5380,5230 v1(5380,5425) 5380,5490 v1(5115,5755) ; v1(5335,5975) 5335,5845 5245,5755 v1(5115,5755)
BOOT0: R3.1 U3.60 | length 226.2
  Top Layer w10: R3.1@4380,4424.4 4428.4,4472.8 U3.60@4428.4,4630.6
C1: SW19.A SW19.B SW20.A SW20.B SW21.A SW21.B SW22.A SW22.B U3.57 | length 2050
  Top Layer w10: SW19.A@3752.1,4088.6 4007.9,4088.6 SW20.A@4155.4,4088.6 SW20.B@4411.3,4088.6 ; U3.57@4369.4,4630.6 4370,4630 4370,4560 4340,4530 4340,4290 4411.3,4218.7 SW20.B@4411.3,4088.6 ; SW22.B@5217.9,4088.6 4962.1,4088.6 SW20.B@4411.3,4088.6
C2: SW3.A SW3.B SW4.A SW4.B SW5.A SW5.B SW6.A SW6.B U3.56 | length 2863.1
  Top Layer w10: U3.56@4349.7,4630.6 4349.7,4559.7 4325,4535 4325,4290 4230,4195 3755,4195 3700,4140 3700,3855.6 3752.1,3803.6 3755.4,3806.9 4962.1,3806.9 SW6.B@5217.9,3806.9
C3: SW7.A SW7.B SW8.A SW8.B SW9.A SW9.B SW10.A SW10.B U3.55 | length 3159
  Top Layer w10: U3.55@4330,4630.6 4332.8,4627.8 4332.8,4562.8 4310,4540 4310,4295 4225,4210 3745,4210 3685,4150 3685,3585.6 3752.1,3518.6 3758.7,3525.2 4962.1,3525.2 SW10.B@5217.9,3525.2
C4: SW11.A SW11.B SW12.A SW12.B SW13.A SW13.B SW14.A SW14.B U3.54 | length 3444.3
  Top Layer w10: U3.54@4310.3,4630.6 4310.3,4560.3 4296,4546 4296,4306 4214,4224 3739.2,4224 3670,4154.8 3670,3315.6 3752.1,3233.6 3762.1,3243.6 4557.1,3243.6 4812.9,3243.6 4962.1,3243.6 SW14.B@5217.9,3243.6
GND: C0.1 C1.1 C2.1 C3.2 C4.1 C5.1 C6.1 C9.1 C10.1 C11.1 C12.1 C13.1 C20.1 C21.1 C32.2 H1.2 H2.4 H3.1 H4.2 H5.4 H8.2 H10.4 LED2.2 Q2.2 R3.2 R4.2 R5.1 R6.2 R8.1 R23.2 R34.1 SW1.C SW1.D SW2.A SW2.B U1.2 U2.1 U3.18 U3.31 U3.47 U3.63 U4.2 USB1.13 USB1.14 USB1.A1B12 USB1.B1A12 X5.2 X5.4 | length 2373.5
  Top Layer w5: U3.63@4487.5,4630.6 4492.8,4635.9 4492.8,4660.2 4512.6,4680 4530,4680 4545,4665 v1(4545,4625)
  Top Layer w7: v1(4635,4745) 4650,4730 4650,4650 4660.9,4639.1 v1(4660.9,4637.4) 4668.3,4630 v1(4700,4630) v1(4765,4630) v1(4830,4630) 4873.9,4630 v1(4882,4638) 4915,4671.1 v1(4915,4690) v1(4915,4750) 4915,4770 4869.9,4815.1 v1(4828.4,4815.1) 4824.9,4815.1 4810,4830 4810,4885 4795,4900 v1(4785,4900) v1(4740,4900) 4737,4897 v1(4695,4897) 4687,4897 4670,4880 4670,4845 v1(4655,4830)
  Top Layer w10: v1(3215,4473.7) 3212.9,4471.7 3212.9,4457.1 3220,4450 3266.6,4450 USB1.14@3276.9,4439.7 3276.9,4462.4 USB1.B1A12@3298.5,4484 ; U3.47@4136.1,4727.1 v1(4205,4727.1) ; R4.2@4199.7,5159.7 4200,5160 v1(4200,5205) ; v1(4230,5030) 4230,5077.8 U3.31@4231.6,5079.4 ; v1(4435,4960) 4435,4985 4487.5,5037.5 U3.18@4487.5,5079.4 ; v1(4485,5175) 4574.8,5175 C5.1@4580.8,5180.9 ; C13.1@4572.9,4447.7 4622.7,4447.7 v1(4630,4455) ; v1(4645,4325) 4645,4308.6 LED2.2@4698.6,4255 ; X5.4@4696.7,4768.5 4716.4,4768.5 X5.2@4783.3,4701.5 4838.3,4756.6 C1.1@4860.8,4756.6 4908.4,4756.6 v1(4915,4750) ; C2.1@4769.5,4851.6 4785,4867.1 v1(4785,4900)
  Bottom Layer w10: v1(4200,5205) 4200,5060 v1(4230,5030) ; v1(4630,4455) 4645,4440 v1(4645,4325)
  other v1: 3495,3435 3533.1,3435 3573.8,3435 3495,3470 3533.1,3470 3572.8,3470 3495,3555 3533.1,3555 3573.8,3555 3495,3590 3533.1,3590 3572.8,3590 3495,3640 3533.1,3640 3573.8,3640 3495,3675 3533.1,3675 3572.8,3675 5390,3815 5428.1,3815 5468.8,3815 5390,3850 5428.1,3850 5467.8,3850 5280,3985 5318.1,3985 5358.8,3985 5280,4020 5318.1,4020 5357.8,4020 6175,4065 6210,4065 6175,4103.1 6210,4103.1 6175,4142.8 6210,4143.8 4435,4390 3215,4505 6410,4630 6448.1,4630 6488.8,4630 6222.2,4635 6261.9,4635 6300,4635 6410,4665 6448.1,4665 6487.8,4665 6221.2,4670 6261.9,4670 6300,4670 3220,4703.4 3220,4740
NRST: C12.2 SW1.A SW1.B U3.7 | length 932
  Top Layer w10: U3.7@4583.9,4825.5 4615.5,4825.5 4655,4865 4655,4892.5 4692.5,4930 4787.5,4930 4825.5,4892 4825.5,4849.5 4840,4835 4869.4,4835 C12.2@4970,4734.4 4997.8,4734.4 5066.4,4802.9 SW1.A@5066.4,4547.1
PA0: H8.1 U3.14 U10.3 | length 2240.7
  Top Layer w10: U3.14@4583.9,4963.3 4585.7,4965 4640,4965 4695,5020 4695,5115 4727.9,5147.9 4997.9,5147.9 5005,5155 5005,5230 5030,5255 U10.3@5073.8,5255 v1(5155,5255)
  Bottom Layer w10: v1(5155,5255) 6166,5255 H8.1@6475.9,4945.1
PA1: U3.15
PA2: H5.2 U3.16 | length 2263.7
  Top Layer w10: U3.16@4583.9,5002.6 4586.6,5000 v1(4640,5000)
  Bottom Layer w10: v1(4640,5000) 4755,5000 5085,4670 5350,4670 5730,4290 6305,4290 H5.2@6480,4115
PA3: H5.3 U3.17 | length 2501
  Top Layer w10: v1(4490,4975.8) 4490,5010 4510,5030 4510,5076.6 U3.17@4507.2,5079.4
  Bottom Layer w10: v1(4490,4975.8) 4759.2,4975.8 5080,4655 5335,4655 5715,4275 6220,4275 H5.3@6480,4015
PA4: U3.20
PA5: U3.21
PA6: U3.22
PA7: U3.23
PA8: H3.3 U3.41 | length 769.7
  Top Layer w10: H3.3@3445,5035 3634.8,4845.2 U3.41@4136.1,4845.2
PA9: H4.4 U3.42 | length 1556.2
  Top Layer w10: v1(3945,4800) 3970.5,4825.5 U3.42@4136.1,4825.5
  Bottom Layer w10: H4.4@3065,3810 3875,4620 3875,4730 v1(3945,4800)
PA10: H4.3 U3.43 | length 1615.8
  Top Layer w10: v1(3955,4755) 4005.8,4805.8 U3.43@4136.1,4805.8
  Bottom Layer w10: H4.3@3065,3710 3155,3800 3155,3880 3890,4615 3890,4690 v1(3955,4755)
